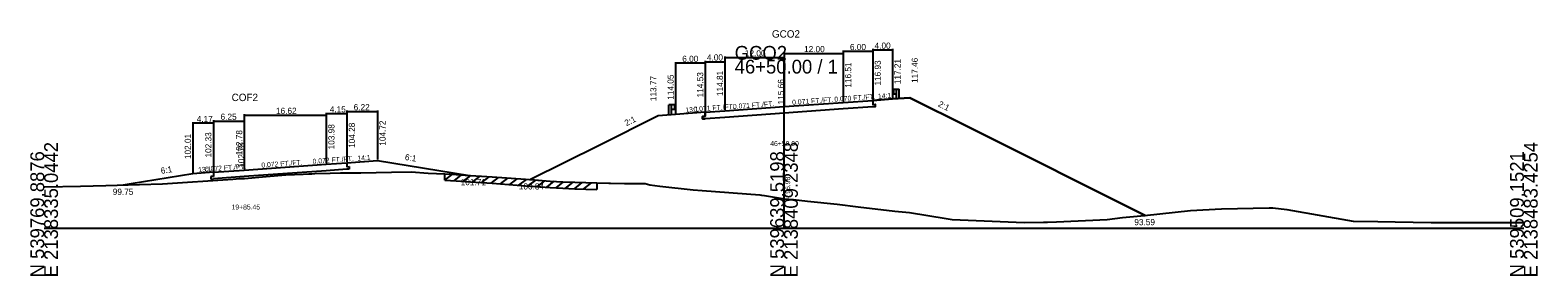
# Model space of a CAD drawing. Extents: x -14327 to 8886, y -10 to 39048.
# Drawn here: x 997.2 to 1302.8, y 32990.3 to 33040.2 of the extents above; entities that cross this region are included whole.
import ezdxf

# ---------------------------------------------------------------- set-up
doc = ezdxf.new("R2010")
doc.units = 0
for name, color, linetype in [('Level 1', 7, 'Continuous'), ('Level 20', 7, 'Continuous'), ('Level 5', 7, 'Continuous'), ('Level 53', 7, 'Continuous'), ('Level 54', 7, 'Continuous'), ('Level 55', 7, 'Continuous'), ('Level 7', 7, 'Continuous'), ('RD_GPK_XS_Cell', 7, 'Continuous'), ('RD_XS_EwShp', 7, 'Continuous'), ('RD_XS_ExGround', 7, 'Continuous'), ('RD_XS_ExPaveRet', 7, 'Continuous'), ('RD_XS_Pave', 7, 'Continuous'), ('RD_XS_TX_Baseline', 7, 'Continuous'), ('RD_XS_TX_Elev_EX', 7, 'Continuous'), ('RD_XS_TX_Elev_PR', 7, 'Continuous'), ('RD_XS_TX_Station', 7, 'Continuous')]:
    doc.layers.add(name, color=color, linetype=linetype)

msp = doc.modelspace()

# ---------------------------------------------------------------- linework, layer by layer
at = {"layer": 'Level 1'}
for p, q in [((1172.02, 33028.03), (1172.14, 33028.12)), ((1172.02, 33027.93), (1172.14, 33027.83)), ((1172.02, 33027.5), (1172.14, 33027.59)), ((1172.02, 33027.4), (1172.14, 33027.3)), ((1172.15, 33028.12), (1172.23, 33028.14)), ((1172.15, 33027.3), (1172.23, 33027.29)), ((1172.16, 33027.79), (1172.16, 33027.63)), ((1172.23, 33028.2), (1172.23, 33027.22)), ((1172.23, 33028.2), (1172.78, 33028.2)), ((1172.23, 33027.22), (1172.78, 33027.22)), ((1172.78, 33026.21), (1172.78, 33028.2)), ((1172.78, 33028.2), (1173.34, 33028.2)), ((1173.34, 33026.21), (1173.34, 33028.2)), ((1126.66, 33023.05), (1126.66, 33025.04)), ((1127.22, 33025.04), (1126.66, 33025.04)), ((1127.22, 33023.05), (1127.22, 33025.04)), ((1127.77, 33025.04), (1127.22, 33025.04)), ((1127.77, 33024.06), (1127.22, 33024.06)), ((1127.77, 33025.04), (1127.77, 33024.06)), ((1127.85, 33024.96), (1127.77, 33024.98)), ((1127.85, 33024.14), (1127.77, 33024.12)), ((1127.84, 33024.63), (1127.84, 33024.47)), ((1127.98, 33024.87), (1127.86, 33024.96)), ((1127.98, 33024.76), (1127.86, 33024.67)), ((1127.98, 33024.34), (1127.86, 33024.43)), ((1127.98, 33024.23), (1127.86, 33024.14))]:
    msp.add_line(p, q, dxfattribs=at)
for centre, radius, start, end in [((1172.07, 33027.98), 0.0651, 129.0336, 230.9663), ((1172.07, 33027.45), 0.0651, 129.0336, 230.9663), ((1172.09, 33027.63), 0.0651, 302.9895, 0), ((1172.15, 33028.1), 0.026, 90, 129.0505), ((1172.09, 33027.79), 0.0651, 0, 45), ((1172.15, 33027.32), 0.026, 230.9496, 270), ((1127.91, 33024.63), 0.0651, 135, 180), ((1127.91, 33024.47), 0.0651, 180, 237.0105), ((1127.85, 33024.94), 0.026, 50.9495, 90), ((1127.85, 33024.16), 0.026, 270, 309.0504), ((1127.93, 33024.81), 0.0651, 309.0337, 50.9664), ((1127.93, 33024.28), 0.0651, 309.0337, 50.9664)]:
    msp.add_arc(centre, radius, start, end, dxfattribs=at)
at = {"layer": 'Level 20'}
for p, q in [((1040.58, 33023.13), (1040.58, 33011.98)), ((1040.58, 33022.93), (1057.2, 33022.93)), ((1057.2, 33023.43), (1057.2, 33013.18)), ((1057.2, 33023.23), (1061.35, 33023.23)), ((1057.2, 33023.13), (1057.2, 33013.18)), ((1061.35, 33023.87), (1061.35, 33013.48)), ((1061.35, 33023.67), (1067.56, 33023.67)), ((1061.35, 33023.43), (1061.35, 33013.48)), ((1067.56, 33023.87), (1067.56, 33013.92)), ((1030.16, 33021.48), (1030.16, 33011.21)), ((1034.33, 33021.28), (1030.16, 33021.28)), ((1034.33, 33021.93), (1034.33, 33011.53)), ((1034.33, 33021.73), (1040.58, 33021.73)), ((1034.33, 33021.48), (1034.33, 33011.53)), ((1040.58, 33021.93), (1040.58, 33011.98)), ((1061.35, 33013.28), (1067.56, 33013.72)), ((1067.56, 33013.72), (1080, 33011.72)), ((1030.16, 33011.01), (1017.65, 33009.01)), ((1034.33, 33011.33), (1030.16, 33011.01)), ((1034.33, 33011.33), (1040.58, 33011.78)), ((1034.33, 33011.33), (1034.33, 33010.5)), ((1040.58, 33011.78), (1057.2, 33012.98)), ((1057.2, 33011.65), (1040.58, 33010.45)), ((1057.2, 33012.98), (1061.35, 33013.28)), ((1061.35, 33011.95), (1057.2, 33011.65)), ((1061.35, 33013.28), (1061.35, 33012.45)), ((1061.35, 33012.45), (1061.87, 33012.49)), ((1061.87, 33011.99), (1061.35, 33011.95)), ((1061.87, 33012.49), (1061.87, 33011.99)), ((1080, 33011.72), (1086.26, 33010.71)), ((1017.65, 33009.01), (1016.01, 33008.75)), ((1034.33, 33010.5), (1033.81, 33010.46)), ((1033.81, 33010.46), (1033.81, 33009.96)), ((1033.81, 33009.96), (1034.33, 33010)), ((1040.58, 33010.45), (1034.33, 33010))]:
    msp.add_line(p, q, dxfattribs=at)
at = {"layer": 'Level 5'}
for p, q in [((1168, 33025.93), (1168, 33025.1)), ((1134, 33023.53), (1134, 33022.7)), ((1150, 33023.33), (1138, 33022.48)), ((1162, 33024.18), (1150, 33023.33)), ((1168, 33024.6), (1162, 33024.18)), ((1168, 33025.1), (1168.5, 33025.13)), ((1168.5, 33024.63), (1168, 33024.6)), ((1168.5, 33025.13), (1168.5, 33024.63)), ((1134, 33022.7), (1133.5, 33022.66)), ((1133.5, 33022.66), (1133.5, 33022.16)), ((1133.5, 33022.16), (1134, 33022.2)), ((1138, 33022.48), (1134, 33022.2))]:
    msp.add_line(p, q, dxfattribs=at)
at = {"layer": 'Level 54'}
for p, q in [((1150, 33035.66), (1150, 33024.86)), ((1150, 33035.46), (1162, 33035.46)), ((1162, 33036.08), (1162, 33025.71)), ((1162, 33035.88), (1168, 33035.88)), ((1162, 33035.66), (1162, 33025.71)), ((1168, 33036.36), (1168, 33026.13)), ((1168, 33036.16), (1172, 33036.16)), ((1168, 33036.08), (1168, 33026.13)), ((1172, 33036.36), (1172, 33026.41)), ((1128, 33033.68), (1128, 33023.25)), ((1134, 33033.48), (1128, 33033.48)), ((1134, 33033.96), (1134, 33023.73)), ((1134, 33033.76), (1138, 33033.76)), ((1134, 33033.68), (1134, 33023.73)), ((1138, 33034.81), (1138, 33024.01)), ((1138, 33034.61), (1150, 33034.61)), ((1138, 33033.96), (1138, 33024.01)), ((1150, 33034.81), (1150, 33024.86))]:
    msp.add_line(p, q, dxfattribs=at)
at = {"layer": 'Level 7'}
for p, q in [((1168, 33025.93), (1172, 33026.21)), ((1172, 33026.21), (1175.5, 33026.46)), ((1175.5, 33026.46), (1187.5, 33020.46)), ((1128, 33023.05), (1124.5, 33022.77)), ((1134, 33023.53), (1128, 33023.05)), ((1124.5, 33022.77), (1112.5, 33016.77)), ((1187.5, 33020.46), (1223.23, 33002.59)), ((1112.5, 33016.77), (1098.63, 33009.84))]:
    msp.add_line(p, q, dxfattribs=at)
at = {"layer": 'RD_GPK_XS_Cell'}
for p, q in [((1150, 33000), (1150, 33034.17)), ((1000, 33000), (1150, 33000)), ((1150, 33000), (1300, 33000))]:
    msp.add_line(p, q, dxfattribs=at)
at = {"layer": 'RD_XS_EwShp'}
msp.add_lwpolyline([(1138, 33022.48), (1134, 33022.2), (1133.5, 33022.16), (1133.5, 33022.66), (1134, 33022.7), (1134, 33023.53), (1128, 33023.05), (1124.5, 33022.77), (1112.5, 33016.77), (1098.63, 33009.84), (1102.56, 33009.56), (1105.19, 33009.38), (1107.6, 33009.3), (1112.03, 33009.16), (1114.49, 33009.09), (1114.8, 33009.13), (1117.68, 33009.05), (1121.83, 33009.03), (1122.82, 33008.79), (1124.84, 33008.49), (1131.6, 33007.79), (1133.41, 33007.62), (1145.09, 33006.73), (1145.43, 33006.69), (1146.06, 33006.6), (1150.11, 33005.96), (1151.91, 33005.78), (1154.77, 33005.46), (1160.75, 33004.87), (1165.02, 33004.29), (1172.45, 33003.41), (1175.45, 33003.14), (1182.88, 33001.95), (1184.09, 33001.77), (1198.67, 33001.15), (1202.6, 33001.2), (1203.39, 33001.18), (1205.27, 33001.3), (1215.49, 33001.75), (1218.65, 33002.13), (1223.12, 33002.58), (1223.23, 33002.59), (1187.5, 33020.46), (1175.5, 33026.46), (1172, 33026.21), (1168, 33025.93), (1168, 33025.1), (1168.5, 33025.13), (1168.5, 33024.63), (1168, 33024.6), (1162, 33024.18), (1150, 33023.33)], close=True, dxfattribs=at)
at = {"layer": 'RD_XS_ExGround'}
for p, q in [((1045.04, 33010.47), (1049.01, 33010.8)), ((1049.01, 33010.8), (1052.5, 33010.97)), ((1052.5, 33010.97), (1053.63, 33011.02)), ((1053.63, 33011.02), (1054.25, 33011.04)), ((1054.25, 33011.04), (1054.86, 33011.07)), ((1054.86, 33011.07), (1058, 33011.15)), ((1058, 33011.15), (1060.11, 33011.23)), ((1060.11, 33011.23), (1064.23, 33011.25)), ((1064.23, 33011.25), (1070.42, 33011.38)), ((1070.42, 33011.38), (1074.42, 33011.39)), ((1074.42, 33011.39), (1077.85, 33011.18)), ((1077.85, 33011.18), (1081.24, 33011.02)), ((1081.24, 33011.02), (1083.51, 33010.88)), ((1083.51, 33010.88), (1085.38, 33010.77)), ((1085.38, 33010.77), (1090.84, 33010.39)), ((1000, 33008.41), (1000.11, 33008.38)), ((1000.11, 33008.38), (1007.38, 33008.5)), ((1007.38, 33008.5), (1012.47, 33008.65)), ((1012.47, 33008.65), (1019.3, 33008.83)), ((1019.3, 33008.83), (1023.96, 33009.02)), ((1023.96, 33009.02), (1038.27, 33009.96)), ((1038.27, 33009.96), (1039.61, 33010.04)), ((1039.61, 33010.04), (1040.59, 33010.1)), ((1040.59, 33010.1), (1045.04, 33010.47)), ((1090.84, 33010.39), (1097.62, 33009.91)), ((1097.62, 33009.91), (1102.56, 33009.56)), ((1102.56, 33009.56), (1105.19, 33009.38)), ((1105.19, 33009.38), (1107.6, 33009.3)), ((1107.6, 33009.3), (1112.03, 33009.16)), ((1112.03, 33009.16), (1114.49, 33009.09)), ((1114.49, 33009.09), (1114.8, 33009.13)), ((1114.8, 33009.13), (1117.68, 33009.05)), ((1117.68, 33009.05), (1121.83, 33009.03)), ((1121.83, 33009.03), (1122.82, 33008.79)), ((1122.82, 33008.79), (1124.84, 33008.49)), ((1124.84, 33008.49), (1131.6, 33007.79)), ((1131.6, 33007.79), (1133.41, 33007.62)), ((1133.41, 33007.62), (1145.09, 33006.73)), ((1145.09, 33006.73), (1145.43, 33006.69)), ((1145.43, 33006.69), (1146.06, 33006.6)), ((1146.06, 33006.6), (1150.11, 33005.96)), ((1150.11, 33005.96), (1151.91, 33005.78)), ((1151.91, 33005.78), (1154.77, 33005.46)), ((1154.77, 33005.46), (1160.75, 33004.87)), ((1160.75, 33004.87), (1165.02, 33004.29)), ((1165.02, 33004.29), (1172.45, 33003.41)), ((1172.45, 33003.41), (1175.45, 33003.14)), ((1175.45, 33003.14), (1182.88, 33001.95)), ((1182.88, 33001.95), (1184.09, 33001.77)), ((1184.09, 33001.77), (1198.67, 33001.15)), ((1205.27, 33001.3), (1215.49, 33001.75)), ((1215.49, 33001.75), (1218.65, 33002.13)), ((1218.65, 33002.13), (1223.12, 33002.58)), ((1223.12, 33002.58), (1232.4, 33003.57)), ((1232.4, 33003.57), (1238.72, 33003.9)), ((1238.72, 33003.9), (1248.37, 33004.09)), ((1248.37, 33004.09), (1249.11, 33004.1)), ((1249.11, 33004.1), (1251.95, 33003.75)), ((1251.95, 33003.75), (1265.4, 33001.42)), ((1265.4, 33001.42), (1270.39, 33001.35)), ((1198.67, 33001.15), (1202.6, 33001.2)), ((1202.6, 33001.2), (1203.39, 33001.18)), ((1203.39, 33001.18), (1205.27, 33001.3)), ((1270.39, 33001.35), (1273.88, 33001.29)), ((1273.88, 33001.29), (1281.23, 33001.12)), ((1281.23, 33001.12), (1299.15, 33001.12)), ((1299.15, 33001.12), (1300, 33001.12))]:
    msp.add_line(p, q, dxfattribs=at)
at = {"layer": 'RD_XS_ExPaveRet'}
for p, q in [((1081.24, 33009.72), (1081.24, 33011.02)), ((1081.24, 33009.72), (1082.76, 33010.93)), ((1083.12, 33009.6), (1084.64, 33010.82)), ((1085, 33009.5), (1086.5, 33010.69)), ((1086.88, 33009.37), (1088.37, 33010.56)), ((1081.24, 33009.72), (1083.51, 33009.58)), ((1083.51, 33009.58), (1085.38, 33009.47)), ((1085.38, 33009.47), (1090.84, 33009.09)), ((1088.76, 33009.23), (1090.25, 33010.43)), ((1090.64, 33009.1), (1092.13, 33010.29)), ((1090.84, 33009.09), (1097.62, 33008.61)), ((1092.51, 33008.97), (1094.01, 33010.16)), ((1094.39, 33008.83), (1095.89, 33010.03)), ((1096.27, 33008.7), (1097.77, 33009.9)), ((1097.62, 33008.61), (1102.56, 33008.26)), ((1098.15, 33008.57), (1099.65, 33009.76)), ((1100.03, 33008.44), (1101.53, 33009.63)), ((1101.91, 33008.31), (1103.4, 33009.5)), ((1102.56, 33008.26), (1105.19, 33008.08)), ((1103.79, 33008.17), (1105.29, 33009.37)), ((1105.19, 33008.08), (1107.6, 33008)), ((1105.66, 33008.06), (1107.23, 33009.31)), ((1107.54, 33008), (1109.11, 33009.25)), ((1107.6, 33008), (1112.03, 33007.86)), ((1109.42, 33007.94), (1110.99, 33009.19)), ((1112.03, 33009.16), (1112.03, 33007.86))]:
    msp.add_line(p, q, dxfattribs=at)
at = {"layer": 'RD_XS_Pave'}
for p, q in [((1162, 33025.51), (1168, 33025.93)), ((1134, 33023.53), (1138, 33023.81)), ((1138, 33023.81), (1150, 33024.66)), ((1150, 33024.66), (1162, 33025.51))]:
    msp.add_line(p, q, dxfattribs=at)

# ---------------------------------------------------------------- texts
at = {"layer": 'Level 20'}
for s, height, p in [('COF2', 1.5, (1038.01, 33025.78)), ('4.17', 1.25, (1030.94, 33021.53)), ('6.25', 1.25, (1035.77, 33021.98)), ('16.62', 1.25, (1047, 33023.18)), ('4.15', 1.25, (1057.9, 33023.48)), ('6.22', 1.25, (1062.75, 33023.92)), ('99.75', 1.25, (1013.91, 33006.75)), ('101.71', 1.25, (1084.45, 33008.71)), ('19+85.45', 1, (1037.99, 33003.78))]:
    msp.add_text(s, height=height, dxfattribs=at).set_placement(p)
for s, height, rotation, p in [('102.78', 1.25, 90, (1040.16, 33014.78)), ('103.98', 1.25, 90, (1058.86, 33015.98)), ('104.28', 1.25, 90, (1063.01, 33016.28)), ('104.72', 1.25, 90, (1069.23, 33016.72)), ('102.01', 1.25, 90, (1029.74, 33014.01)), ('102.33', 1.25, 90, (1033.91, 33014.33)), (' 102.78', 1.25, 90, (1040.58, 33011.78)), ('0.072 FT./FT.', 1, 4.1399, (1044.07, 33012.28)), ('0.072 FT./FT.', 1, 4.1456, (1054.46, 33013.04)), ('14:1', 1, 4.0021, (1063.54, 33013.69)), ('6:1', 1.25, 350.8606, (1073.07, 33013.85)), ('6:1', 1.25, 9.0813, (1023.74, 33011)), ('13:1', 1, 4.3873, (1031.27, 33011.34)), ('0.072 FT./FT.', 1, 4.1331, (1032.63, 33011.46))]:
    msp.add_text(s, height=height, rotation=rotation, dxfattribs=at).set_placement(p)
at = {"layer": 'Level 53'}
for s, rotation, p in [('116.51', 90, (1163.63, 33028.51)), ('116.93', 90, (1169.63, 33028.93)), ('117.21', 90, (1173.63, 33029.21)), ('117.46', 90, (1177.13, 33029.46)), ('113.77', 90, (1124.13, 33025.77)), ('114.05', 90, (1127.63, 33026.05)), ('114.53', 90, (1133.63, 33026.53)), ('114.81', 90, (1137.63, 33026.81)), ('2:1', 333.4349, (1181.11, 33024.77)), ('2:1', 26.5651, (1118.05, 33020.66))]:
    msp.add_text(s, height=1.25, rotation=rotation, dxfattribs=at).set_placement(p)
for s, p in [('100.84', (1096.24, 33007.84)), ('93.59', (1221.03, 33000.59))]:
    msp.add_text(s, height=1.25, dxfattribs=at).set_placement(p)
at = {"layer": 'Level 54'}
for s, p in [('6.00', (1129.37, 33033.73)), ('4.00', (1134.37, 33034.01)), ('12.00', (1142.07, 33034.86)), ('12.00', (1154.07, 33035.71)), ('6.00', (1163.37, 33036.13)), ('4.00', (1168.37, 33036.41))]:
    msp.add_text(s, height=1.25, dxfattribs=at).set_placement(p)
at = {"layer": 'Level 55'}
for s, rotation, p in [('0.071 FT./FT.', 4.0467, (1151.68, 33025.03)), ('0.070 FT./FT.', 4.007, (1160.24, 33025.64)), ('14:1', 4.007, (1169.08, 33026.26)), ('13:1', 4.5739, (1130.03, 33023.46)), ('0.071 FT./FT.', 4.0467, (1131.68, 33023.62)), ('0.071 FT./FT.', 4.0467, (1139.68, 33024.18))]:
    msp.add_text(s, height=1, rotation=rotation, dxfattribs=at).set_placement(p)
at = {"layer": 'RD_GPK_XS_Cell'}
for s, p in [('GCO2', (1140, 33034.17)), ('46+50.00 / 1', (1140, 33031.37))]:
    msp.add_text(s, height=2.8, dxfattribs=at).set_placement(p)
for s, p in [('E 2138335.0442', (1002.8, 32990)), ('E 2138409.2348', (1152.8, 32990)), ('E 2138483.4254', (1302.8, 32990)), ('N 539769.8876', (1000, 32990)), ('N 539639.5198', (1150, 32990)), ('N 539509.1521', (1300, 32990))]:
    msp.add_text(s, height=2.8, rotation=90, dxfattribs=at).set_placement(p)
at = {"layer": 'RD_XS_TX_Baseline'}
msp.add_text('GCO2', height=1.5, dxfattribs=at).set_placement((1147.55, 33038.66))
at = {"layer": 'RD_XS_TX_Elev_EX'}
msp.add_text('96.98', height=1, rotation=90, dxfattribs=at).set_placement((1151.25, 33006.98))
at = {"layer": 'RD_XS_TX_Elev_PR'}
msp.add_text(' 115.66', height=1.25, rotation=90, dxfattribs=at).set_placement((1150, 33024.66))
at = {"layer": 'RD_XS_TX_Station'}
msp.add_text('46+50.00', height=1, dxfattribs=at).set_placement((1147.21, 33016.66))

doc.saveas('drawing.dxf')
